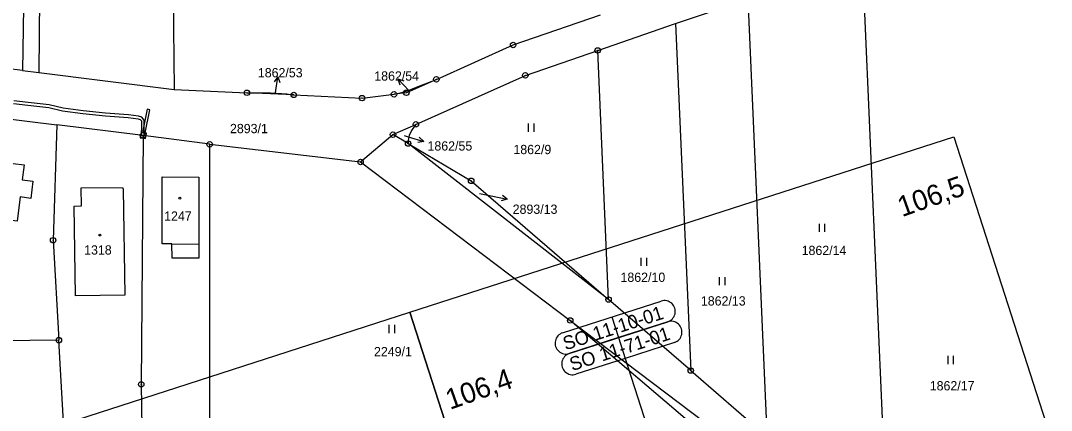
# Model space of a CAD drawing. Extents: x -758836 to -757729, y -1175316 to -1174366.
# Drawn here: x -758289.2 to -758099.9, y -1174708.8 to -1174637.3 of the extents above; entities that cross this region are included whole.
import ezdxf

# ---------------------------------------------------------------- set-up
doc = ezdxf.new("R2010")
doc.units = 0
for name, color, linetype in [('_NOR-pomocná', 7, 'Continuous'), ('_NOR-popis', 7, 'Continuous'), ('Hranice parcel', 7, 'Continuous'), ('Parcelní čísla', 7, 'Continuous'), ('Pop  PČ popisy', 7, 'Continuous'), ('Vnitřní kresba', 7, 'Continuous'), ('Vrstva 7', 7, 'Continuous'), ('Věcná břemena k části', 7, 'Continuous'), ('Značky bodu BP', 7, 'Continuous'), ('Značky budov', 7, 'Continuous'), ('Značky kultur', 7, 'Continuous')]:
    doc.layers.add(name, color=color, linetype=linetype)

msp = doc.modelspace()

# ---------------------------------------------------------------- linework, layer by layer
at = {"layer": '_NOR-pomocná'}
for p, q in [((-758180.62, -1174691.68), (-758179.39, -1174695.49)), ((-758179.39, -1174695.49), (-758178.16, -1174699.3))]:
    msp.add_line(p, q, dxfattribs=at)
for points in [[(-758217.71, -1174690.84), (-758117.77, -1174658.65), (-758072.24, -1174800), (-758172.18, -1174832.19)], [(-758317.65, -1174723.03), (-758217.71, -1174690.84), (-758172.18, -1174832.19), (-758272.12, -1174864.38)]]:
    msp.add_lwpolyline(points, close=True, dxfattribs=at)
at = {"layer": '_NOR-popis'}
for points in [[(-758189.66, -1174694.59), (-758171.57, -1174688.77)], [(-758188.43, -1174698.4), (-758170.35, -1174692.58)], [(-758170.35, -1174692.58), (-758179.39, -1174695.49)], [(-758179.39, -1174695.49), (-758188.43, -1174698.4)], [(-758169.12, -1174696.38), (-758178.16, -1174699.3), (-758157.53, -1174763.36)], [(-758178.16, -1174699.3), (-758187.21, -1174702.21)]]:
    msp.add_lwpolyline(points, dxfattribs=at)
for centre, start, end in [((-758170.96, -1174690.67), 287.8533, 107.854), ((-758169.73, -1174694.48), 287.8533, 107.854), ((-758189.04, -1174696.5), 107.854, 287.8547), ((-758187.82, -1174700.31), 107.854, 287.8547)]:
    msp.add_arc(centre, 2, start, end, dxfattribs=at)
at = {"layer": 'Hranice parcel'}
for p, q in [((-758285.46, -1174607.47), (-758285.9, -1174646.82)), ((-758261.42, -1174607.5), (-758261.03, -1174649.91)), ((-758134.62, -1174626.06), (-758130.45, -1174721.94)), ((-758168.89, -1174637.84), (-758155.57, -1174633.26)), ((-758152.07, -1174713.65), (-758155.57, -1174633.26)), ((-758183.21, -1174642.76), (-758168.89, -1174637.84)), ((-758168.89, -1174637.84), (-758166.12, -1174701.53)), ((-758181.22, -1174688.49), (-758183.21, -1174642.76)), ((-758288.89, -1174646.43), (-758291.89, -1174646.05)), ((-758288.89, -1174646.43), (-758285.9, -1174646.82)), ((-758285.9, -1174646.82), (-758261.03, -1174649.91)), ((-758261.03, -1174649.91), (-758247.67, -1174650.53)), ((-758239.06, -1174650.93), (-758247.67, -1174650.53)), ((-758303.07, -1174653.93), (-758282.56, -1174656.41)), ((-758266.75, -1174658.35), (-758282.56, -1174656.41)), ((-758220.83, -1174658.22), (-758216.61, -1174656.33)), ((-758254.5, -1174659.99), (-758266.75, -1174658.35)), ((-758226.78, -1174663.24), (-758220.83, -1174658.22)), ((-758218.05, -1174659.86), (-758220.83, -1174658.22)), ((-758254.45, -1174715.89), (-758254.5, -1174659.99)), ((-758254.5, -1174659.99), (-758226.78, -1174663.24)), ((-758181.22, -1174688.49), (-758218.05, -1174659.86)), ((-758226.78, -1174663.24), (-758188.26, -1174692.33)), ((-758166.12, -1174701.53), (-758181.22, -1174688.49)), ((-758149.09, -1174725.67), (-758188.26, -1174692.33)), ((-758281.06, -1174716.22), (-758282.22, -1174695.95)), ((-758166.12, -1174701.53), (-758152.07, -1174713.65))]:
    msp.add_line(p, q, dxfattribs=at)
for points in [[(-758288.91, -1174575.86), (-758288.5, -1174594.53), (-758288.43, -1174615.42), (-758288.89, -1174646.43)], [(-758212.86, -1174648.07), (-758198.75, -1174641.76), (-758182.68, -1174636.24)], [(-758216.61, -1174656.33), (-758196.5, -1174647.34), (-758183.21, -1174642.76)], [(-758220.63, -1174650.81), (-758219.98, -1174650.66), (-758219, -1174650.41), (-758218.05, -1174650.11), (-758217.1, -1174649.77), (-758216.19, -1174649.41), (-758212.86, -1174648.07)], [(-758212.86, -1174648.07), (-758218.37, -1174650.54), (-758220.63, -1174650.81)], [(-758247.67, -1174650.53), (-758245.32, -1174650.56), (-758243.31, -1174650.57), (-758242.31, -1174650.6), (-758241.31, -1174650.66), (-758240.32, -1174650.75), (-758239.33, -1174650.89), (-758239.06, -1174650.93)], [(-758239.06, -1174650.93), (-758226.51, -1174651.52), (-758220.63, -1174650.81)], [(-758282.22, -1174695.95), (-758303.68, -1174696.21), (-758304.17, -1174686.81), (-758304.54, -1174655.43), (-758303.04, -1174655.41), (-758303.07, -1174653.93)], [(-758282.56, -1174656.41), (-758283.27, -1174677.6), (-758282.22, -1174695.95)], [(-758216.61, -1174656.33), (-758216.89, -1174656.64), (-758217.45, -1174657.45), (-758217.83, -1174658.36), (-758218.03, -1174659.32), (-758218.05, -1174659.86)], [(-758266.75, -1174658.35), (-758267.08, -1174704.07), (-758266.93, -1174716.05)], [(-758218.05, -1174659.86), (-758206.46, -1174666.7), (-758181.22, -1174688.49)], [(-758298.73, -1174662.53), (-758288.59, -1174663.75), (-758288.93, -1174666.52), (-758286.98, -1174666.77), (-758287.37, -1174669.93), (-758289.32, -1174669.66), (-758289.87, -1174674.12), (-758300.02, -1174672.9), (-758298.73, -1174662.53)], [(-758261.43, -1174678.26), (-758263.22, -1174678.26), (-758263.23, -1174665.98), (-758256.5, -1174666.04), (-758256.48, -1174678.31), (-758256.48, -1174680.88), (-758261.39, -1174680.88), (-758261.43, -1174678.26)], [(-758278.1, -1174667.99), (-758270.51, -1174667.9), (-758270.38, -1174668.23), (-758270.07, -1174687.69), (-758279.14, -1174687.84), (-758279.41, -1174671.35), (-758278.04, -1174671.32), (-758278.1, -1174667.99)], [(-758188.26, -1174692.33), (-758148.33, -1174722.48), (-758149.09, -1174725.67)]]:
    msp.add_lwpolyline(points, dxfattribs=at)
at = {"layer": 'Pop  PČ popisy'}
for p, q in [((-758241.99, -1174647.6), (-758242.63, -1174648.52)), ((-758242.41, -1174650.57), (-758241.99, -1174647.6)), ((-758241.99, -1174647.6), (-758241.64, -1174648.66)), ((-758217.83, -1174650.15), (-758219.92, -1174647.99)), ((-758219.92, -1174647.99), (-758218.86, -1174648.36)), ((-758219.92, -1174647.99), (-758219.58, -1174649.06)), ((-758242.44, -1174650.73), (-758242.41, -1174650.57)), ((-758218.78, -1174658.37), (-758218.05, -1174658.6)), ((-758218.05, -1174658.6), (-758215.18, -1174659.48)), ((-758215.18, -1174659.48), (-758215.99, -1174658.71)), ((-758215.18, -1174659.48), (-758216.28, -1174659.66)), ((-758204.92, -1174669.01), (-758202.79, -1174669.45)), ((-758202.79, -1174669.45), (-758199.85, -1174670.07)), ((-758199.85, -1174670.07), (-758200.94, -1174670.36)), ((-758199.85, -1174670.07), (-758200.73, -1174669.38))]:
    msp.add_line(p, q, dxfattribs=at)
at = {"layer": 'Vnitřní kresba'}
msp.add_line((-758261.43, -1174678.26), (-758256.48, -1174678.31), dxfattribs=at)
at = {"layer": 'Věcná břemena k části'}
msp.add_lwpolyline([(-758290.55, -1174652.5), (-758287.93, -1174652.83), (-758284.09, -1174653.22), (-758281.54, -1174653.85), (-758277.79, -1174654.36), (-758273.67, -1174654.75), (-758269.46, -1174655.1), (-758267.66, -1174655.34), (-758267.25, -1174655.43), (-758267.04, -1174655.71), (-758267.06, -1174656.84), (-758267.07, -1174657.98), (-758267.02, -1174658.32), (-758266.75, -1174658.35), (-758266.5, -1174658.38), (-758266.57, -1174657.94), (-758266.56, -1174656.84), (-758266.54, -1174655.55), (-758266.95, -1174654.99), (-758267.56, -1174654.84), (-758269.4, -1174654.6), (-758273.63, -1174654.25), (-758277.73, -1174653.86), (-758281.44, -1174653.35), (-758284.01, -1174652.72), (-758287.87, -1174652.33), (-758290.49, -1174652)], dxfattribs=at)
for points in [[(-758267.19, -1174658.3), (-758266.75, -1174658.35), (-758266.2, -1174658.42), (-758266.1, -1174657.93), (-758266.34, -1174657.9), (-758265.48, -1174653.64), (-758265.97, -1174653.54), (-758266.84, -1174657.84), (-758267.09, -1174657.81)], [(-758266.75, -1174658.85), (-758266.75, -1174658.35), (-758267.02, -1174658.32), (-758267.19, -1174658.3), (-758267.26, -1174658.79)], [(-758266.5, -1174658.38), (-758266.75, -1174658.35), (-758266.75, -1174658.85), (-758266.27, -1174658.92), (-758266.2, -1174658.42)]]:
    msp.add_lwpolyline(points, close=True, dxfattribs=at)
at = {"layer": 'Značky bodu BP'}
for centre, radius in [((-758198.75, -1174641.76), 0.5), ((-758198.75, -1174641.76), 0.0303), ((-758183.21, -1174642.76), 0.5), ((-758183.21, -1174642.76), 0.0303), ((-758212.86, -1174648.07), 0.5), ((-758196.5, -1174647.34), 0.5), ((-758196.5, -1174647.34), 0.0303), ((-758212.86, -1174648.07), 0.0303), ((-758247.67, -1174650.53), 0.5), ((-758247.67, -1174650.53), 0.0303), ((-758239.06, -1174650.93), 0.5), ((-758239.06, -1174650.93), 0.0303), ((-758226.51, -1174651.52), 0.5), ((-758220.63, -1174650.81), 0.5), ((-758220.63, -1174650.81), 0.0303), ((-758218.37, -1174650.54), 0.5), ((-758218.37, -1174650.54), 0.0303), ((-758226.51, -1174651.52), 0.0303), ((-758216.61, -1174656.33), 0.5), ((-758216.61, -1174656.33), 0.0303), ((-758266.75, -1174658.35), 0.5), ((-758266.75, -1174658.35), 0.0303), ((-758220.83, -1174658.22), 0.5), ((-758220.83, -1174658.22), 0.0303), ((-758254.5, -1174659.99), 0.5), ((-758254.5, -1174659.99), 0.0303), ((-758218.05, -1174659.86), 0.5), ((-758218.05, -1174659.86), 0.0303), ((-758226.78, -1174663.24), 0.5), ((-758226.78, -1174663.24), 0.0303), ((-758206.46, -1174666.7), 0.5), ((-758206.46, -1174666.7), 0.0303), ((-758283.27, -1174677.6), 0.5), ((-758283.27, -1174677.6), 0.0303), ((-758181.22, -1174688.49), 0.5), ((-758181.22, -1174688.49), 0.0303), ((-758188.26, -1174692.33), 0.5), ((-758188.26, -1174692.33), 0.0303), ((-758282.22, -1174695.95), 0.5), ((-758282.22, -1174695.95), 0.0303), ((-758166.12, -1174701.53), 0.5), ((-758166.12, -1174701.53), 0.0303), ((-758267.08, -1174704.07), 0.5), ((-758267.08, -1174704.07), 0.0303)]:
    msp.add_circle(centre, radius, dxfattribs=at)
at = {"layer": 'Značky budov'}
for centre in [(-758260, -1174669.88), (-758274.71, -1174676.65)]:
    msp.add_circle(centre, 0.175, dxfattribs=at)
at = {"layer": 'Značky kultur'}
for p, q in [((-758195.9, -1174657.7), (-758195.9, -1174656.2)), ((-758194.9, -1174657.7), (-758194.9, -1174656.2)), ((-758142.48, -1174676.09), (-758142.48, -1174674.59)), ((-758141.48, -1174676.09), (-758141.48, -1174674.59)), ((-758175.21, -1174682.32), (-758175.21, -1174680.82)), ((-758174.21, -1174682.32), (-758174.21, -1174680.82)), ((-758160.82, -1174685.88), (-758160.82, -1174684.38)), ((-758159.82, -1174685.88), (-758159.82, -1174684.38)), ((-758221.5, -1174694.66), (-758221.5, -1174693.16)), ((-758220.5, -1174694.66), (-758220.5, -1174693.16)), ((-758118.81, -1174700.34), (-758118.81, -1174698.84)), ((-758117.81, -1174700.34), (-758117.81, -1174698.84))]:
    msp.add_line(p, q, dxfattribs=at)

# ---------------------------------------------------------------- texts
at = {"layer": '_NOR-popis'}
for s, p in [('SO 11-10-01', (-758189.13, -1174697.84)), ('SO 11-71-01', (-758187.91, -1174701.65))]:
    msp.add_text(s, height=2.5, rotation=17.854, dxfattribs=at).set_placement(p)
at = {"layer": 'Parcelní čísla'}
for s, p in [('1862/53', (-758245.65, -1174647.7)), ('1862/54', (-758224.26, -1174648.3)), ('2893/1', (-758250.77, -1174657.95)), ('1862/55', (-758214.48, -1174661.14)), ('1862/9', (-758198.7, -1174661.8)), ('1247', (-758262.87, -1174674.02)), ('2893/13', (-758198.83, -1174672.76)), ('1318', (-758277.57, -1174680.24)), ('1862/14', (-758145.74, -1174680.32)), ('1862/10', (-758179.02, -1174685.25)), ('1862/13', (-758164.25, -1174689.59)), ('2249/1', (-758224.31, -1174698.9)), ('1862/17', (-758122.2, -1174705.17))]:
    msp.add_text(s, height=1.7, dxfattribs=at).set_placement(p)
at = {"layer": 'Vrstva 7'}
for s, p in [('106,5', (-758127.3, -1174673.38)), ('106,4', (-758210.35, -1174708.76))]:
    msp.add_text(s, height=3.75, rotation=19.4575, dxfattribs=at).set_placement(p)

doc.saveas('drawing.dxf')
